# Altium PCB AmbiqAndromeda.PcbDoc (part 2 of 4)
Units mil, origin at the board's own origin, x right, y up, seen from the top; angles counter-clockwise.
Board outline 4055.04 x 2407.2 mil, 6 copper layers (Layer 1, Layer 2, Layer 3, Layer 4, Layer 5, Layer 6), stack 76.457 mil thick; 255 components, 215 nets, 1186 pads, 683 vias.
Unrouted connection lines stored in the file: 258.
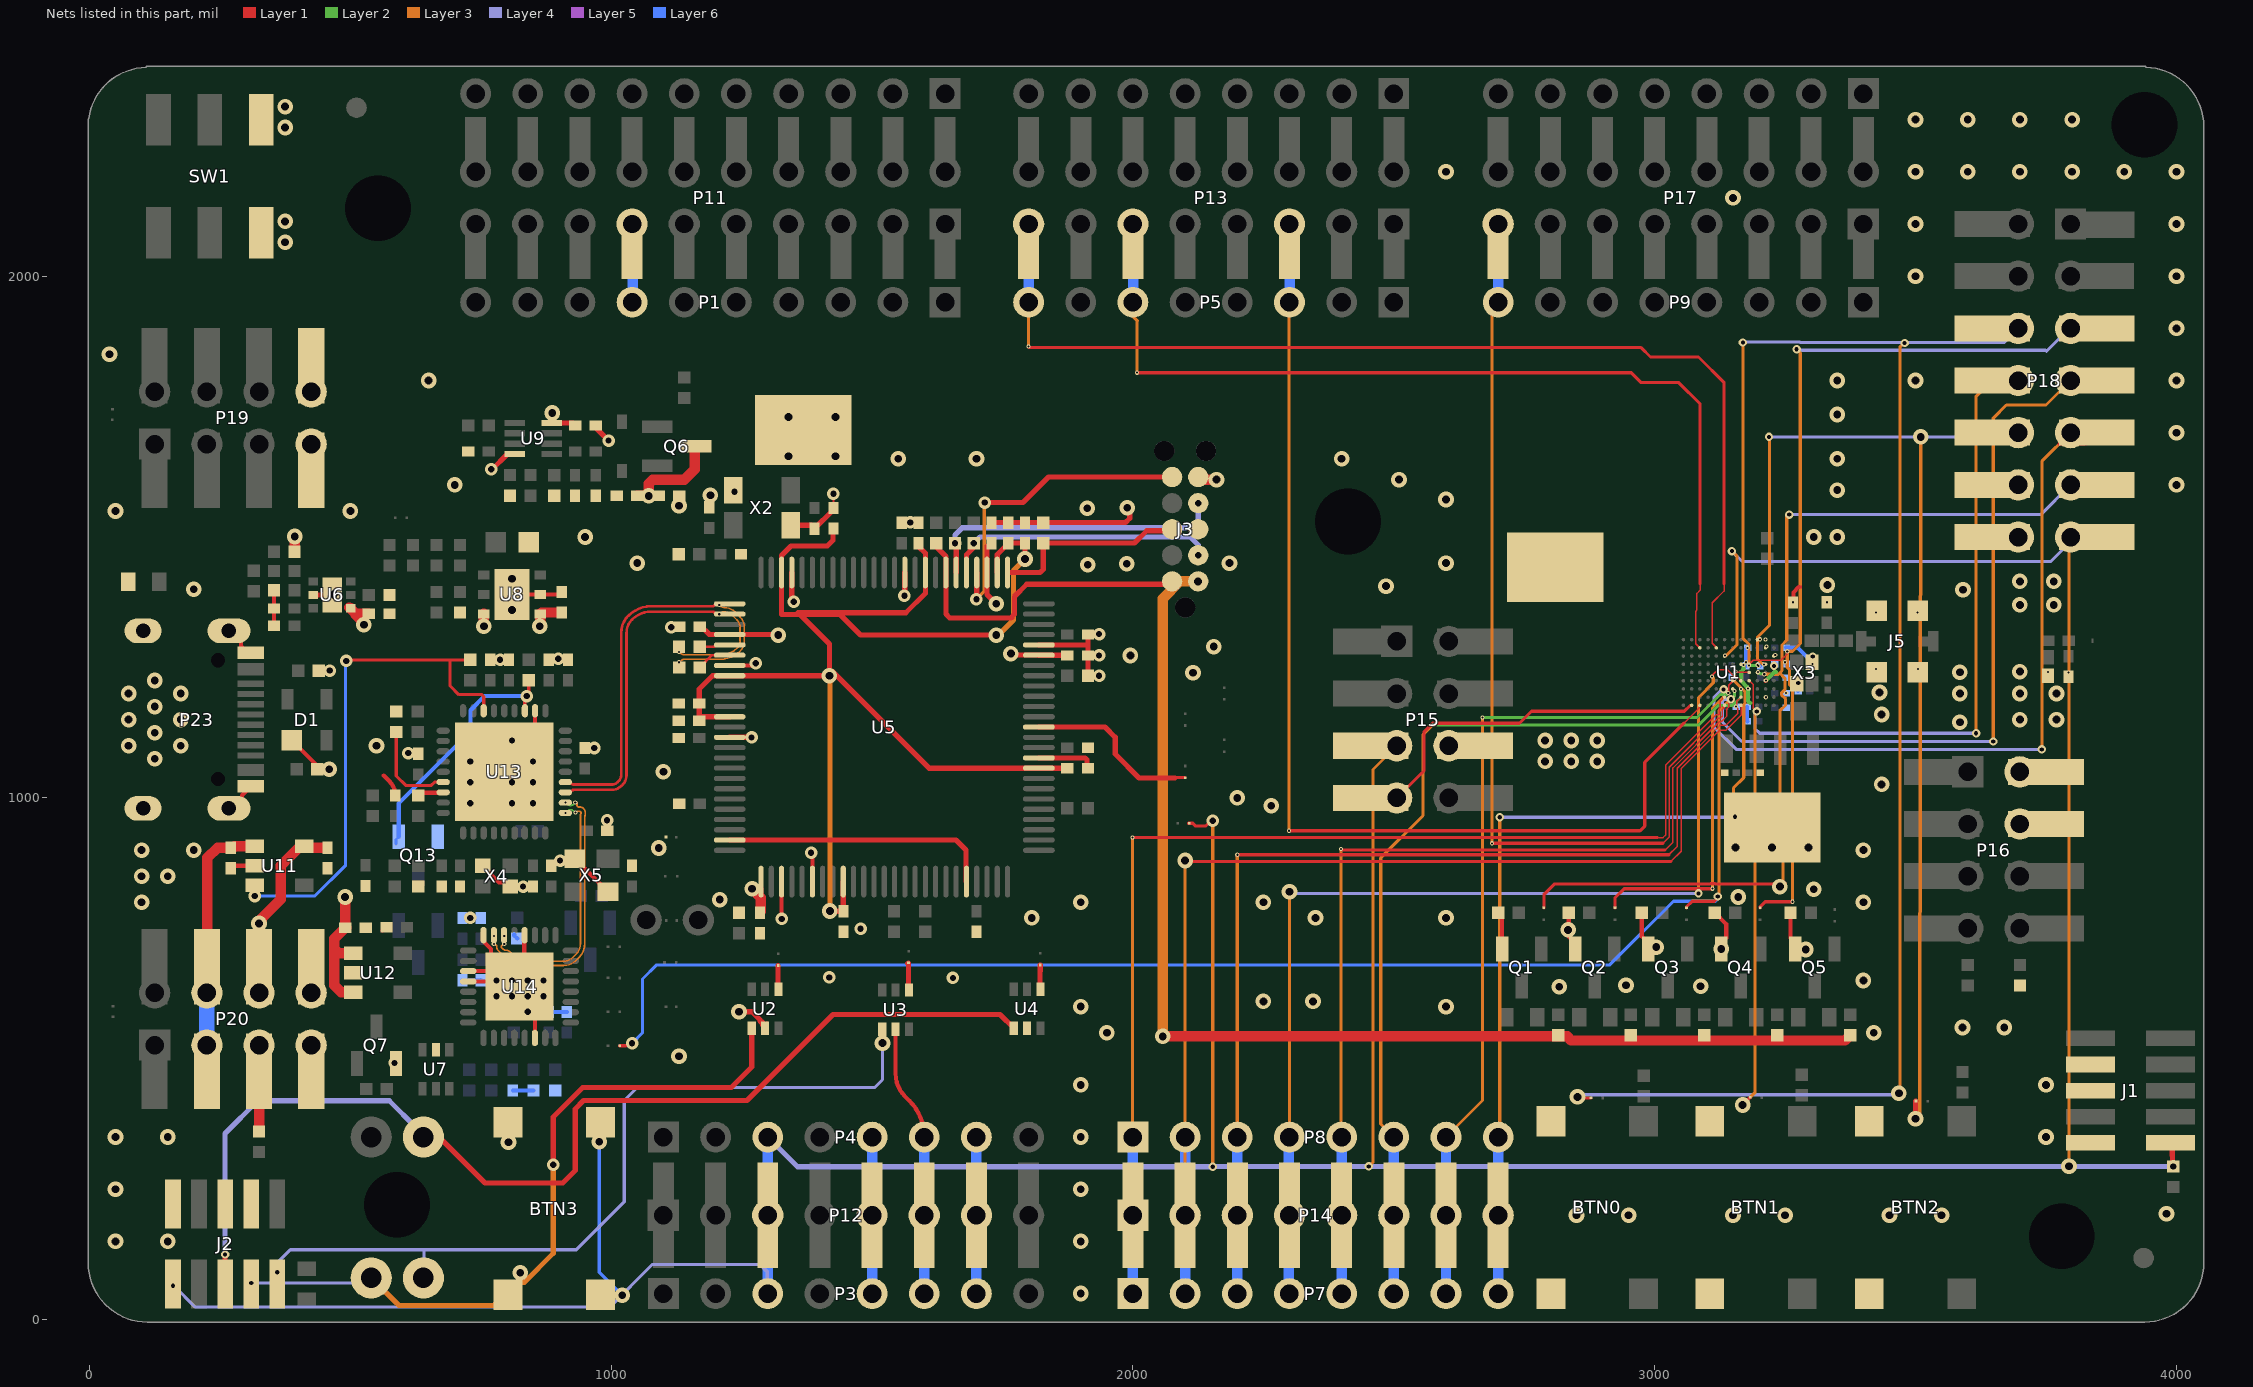
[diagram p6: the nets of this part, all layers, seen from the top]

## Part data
A1: library part ANT_PCB, "2.4G Printed Antenna"
BTN0 BTN1 BTN2 BTN3: library part TACT_4PIN, "Tactile Switch SPST-NO Top Actuated Surface Mount"
C1 C2 C3 C4 C5 C6 C7 C8 C9 C10 C11 C12 C13 C14 C15 C16 C17 C18 C19 C20 C21 C22 C23 C24 C25 C26 C27 C28 C29 C30 C31 C32 C33 C34 C35 C36 C37 C38 C39 C40 C41 C42 C43 C44 C45 C46 C47 C48 C49 C50 C51 C54 C55 C56 C57 C58 C59 C60 C61 C62 C63 C64 C65 C66 C67 C68 C69 C70 C71 C72 C73 C74 C78 C79 C80 C81 C82 C83 C84: library part CAP_CHP, "Surface Mount Unpolarized Capacitor"
D1: "Ultra low capacitance double rail-to-rail ESD protection diode"
D2 D3 D5 D6 D7 D8 D9: library part LED_SMD, "Surface Mount LED"
D70: library part SKT_SMD, "Surface Mount Diode"
FB1: library part FBD_CHP, "Surface Mount Ferrite Bead"
J1 J2: library part FTSH-105, "10 Positions Header, Unshrouded Connector 1.27mm SMD Gold"
J5: "SWD Connector Receptacle, Female Socket 50 Ohm Surface Mount Solder"
L1: library part IND_PWR, "DFE201610E-2R2M=P2"
L2: library part IND_PWR, "DFE18SAN1R0MG0L"
L3 L4 L5: library part IND_CHP, "Chip Inductor"
P1 P2: library part HDR1X10
P3 P4 P5 P6 P7 P8 P9 P10: library part HDR1X8
P11: library part SSM-110-L-DV-P-TR_2, "20 Position Receptacle, Pass Through Connector 2.54mm Gold SMD"
P12 P14: "8 Position Receptacle, Pass Through Connector 2.54mm Gold SMD"
P13 P17: library part SSM-108-L-DV-P-TR_2, "16 Position Receptacle, Pass Through Connector 2.54mm Gold SMD"
P15 P16 P19 P20: "8 Positions Header, 2 Row,Gold, Unshrouded Connector 2.54mm SMD"
P18: "14 Positions Socket Strip, Double Row Vertical 2,54mm SMD"
P21 P22: "SMT Fiducial"
P23: "USB Type-C Connector"
Q1 Q2 Q3 Q4 Q5 Q13: library part MOS_N, "N-Channel MOSFET"
Q6 Q7: library part TRAN_NPN, "Surface Mount NPN Transistor"
Q11 Q12: library part MOS_P, "P-Channel MOSFET"
R1 R2 R3 R4 R5 R6 R7 R8 R9 R10 R11 R12 R13 R14 R15 R16 R17 R18 R19 R20 R21 R22 R23 R26 R27 R28 R29 R30 R31 R32 R33 R34 R35 R36 R37 R38 R39 R40 R41 R42 R43 R44 R45 R46 R47 R48 R49 R50 R51 R52 R53 R54 R55 R56 R57 R58 R59 R60 R61 R62 R79 R80 R81 R82 R86: library part RES_CHP, "Surface Mount Resistor"
SB1 SB3 SB5 SB7 SB8 SB9 SB10 SB11 SB12 SB13 SB14 SB17 SB18 SB19 SB20 SB21 SB22 SB23 SB24 SB25 SB26 SB27 SB84: "Short-circuit soldering bridge"
SB4 SB6 SB15 SB16 SB85: "Open-circuit soldering bridge"
SW1: "Slide Switch DPDT Surface Mount 9x3.5x3.5  Pitch=2.5mm"
TP1 TP2 TP3 TP4: library part TP
TP6 TP7 TP8: library part TP, "Test Point"
U1: library part APOLLO3BP-BGA, "APOLLO3 Blue Plus", Manufacturer="Ambiq Micro"
U2 U3 U4: "2-channel analog multiplexer/demultiplexer"
U5: library part ATSAM3U2CA, "Atmel"
U6: library part NCP380, "IC CURRENT LIMIT SWITCH UDFN6"
U7: library part 74LVC2G04, "Dual Inverter"
U8: "Voltage Regulator, 1A, Low Quiescent Current  ,DFN6 Tape&Reel"
U9: library part MAX44263, "General Purpose Amplifier 2 Circuit Rail-to-Rail"
U11 U12: "Linear Voltage Regulator Positive Fixed 1 Output 3.3V 300mA SOT-23-5"
U13: library part USB2512B, "USB 2.0 High-Speed 2-Port Hub Controller"
U14: library part FT4222, "FT4222H USB2.0 TO QUADSPI/I2C BRIDGE IC"
X1: "32.768KHZ IoT OPTIMIZED SMD CRYSTA"
X2: library part XTAL_SMD_4PIN, "XTAL 12MHz ±30ppm 18pF 100 Ohm -20°C ~ 70°C SMD 3225"
X3: library part ECX-1247, "XTAL 32MHZ 8pF 20ppm  1.6mm x 1.2mm x 0.35mm SMT"
X4 X5: library part XTAL_SMD_4PIN, "Surface Mount Crystal"

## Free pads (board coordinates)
  round 60 hole 35.43: 1(1167,766) 2(1067,766)
  rect 23.62x57.09 hole 125.98 unplated: MH(553,2130) MH(589.37,220) MH(2412,1530) MH(3780,160) MH(3939,2290)

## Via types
v1: diameter 30, hole 15, Layer 1 to Layer 6, tented both sides, 227 vias
v2: diameter 8, hole 4, Layer 1 to Layer 2, tented both sides, 113 vias
v3: diameter 8, hole 4, Layer 2 to Layer 3, tented both sides, 98 vias
v4: diameter 24, hole 12, Layer 1 to Layer 6, tented both sides, 91 vias
v5: diameter 16, hole 8, Layer 3 to Layer 4, tented both sides, 71 vias
v6: diameter 8, hole 4, Layer 5 to Layer 6, tented both sides, 26 vias
v7: diameter 16, hole 8, Layer 1 to Layer 6, tented both sides, 25 vias
v8: diameter 8, hole 4, Layer 4 to Layer 5, tented both sides, 20 vias
v9: diameter 8, hole 4, Layer 1 to Layer 2, 4 vias
v10: diameter 8, hole 4, Layer 2 to Layer 3, 4 vias
v11: diameter 16/16/16/16/16/16 (per signal layer), hole 8, Layer 1 to Layer 6, tented both sides, 2 vias
v12: diameter 24/0/0/24/24/24 (per signal layer), hole 12, Layer 1 to Layer 6, tented both sides, 1 vias
v13: diameter 30/0/0/30/30/30 (per signal layer), hole 15, Layer 1 to Layer 6, tented both sides, 1 vias

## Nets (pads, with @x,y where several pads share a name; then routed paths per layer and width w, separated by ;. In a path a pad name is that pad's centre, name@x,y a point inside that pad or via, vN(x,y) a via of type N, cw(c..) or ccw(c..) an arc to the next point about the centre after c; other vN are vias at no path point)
5V_USB: C32.2 C34.2 C36.2 C50.2 C79.2 C81.2 C82.2 J3.5 P3.5 P4.5 P12.5 P20.3 P20.4 Q6.3 R19.1 U6.1 U8.1 U8.6 U9.8 U11.1 U12.1 U12.3 | length 1483.3
  Layer 1 w10: U9.8@885.93,1718.43 U9.8@886.16,1718.43 ; v1(887,1737.65) 887,1720.18 887.46,1719.73 U9.8@886.16,1718.43 ; C79.2@930.82,1713.9 926.29,1718.43 U9.8@886.16,1718.43
  Layer 1 w20: P20.4@220,720 226,726 226,885 245.69,904.69 C34.2@271,904.69 275.69,904.69 C34.2@276,905 ; P20.4@224,713 220,709 220,681.25 P20.4@225,676.25 ; C34.2@277,906 278.4,907.4 U11.1@317,907.4 ; R19.1@392.92,1471.99 R19.1@393.33,1471.99 ; R19.1@393.33,1472.01 v1(393.33,1501) ; 475.04,705 477.64,702.4 U12.1@505.76,702.4 ; v1(490,810) 490,751.16 C50.2@490.16,751 ; C50.2@492.13,750.84 491.97,751 C50.2@490.31,751 C50.2@490.16,751 ; U6.1@498,1365 U6.1@499.59,1363.41 ; U6.1@500.93,1363.41 U6.1@499.59,1363.41 ; U12.3@505.76,627.6 482.4,627.6 469,641 469,729.69 488.5,749.19 488.5,750.84 488.66,751 C50.2@490.16,751 ; v1(526,1332) 526,1334.71 510.01,1350.7 510.01,1352.99 ; C32.2@535.55,1352.99 510.01,1352.99 ; v1@755,1328 v1(755.87,1328.87) U8.6@755.87,1352.6 ; v1@864.13,1329 U8.1@864.13,1352.6 866.85,1355.31 C36.2@905,1355.31 ; C81.2@1050.19,1578.9 v1(1072,1578.9) 1072,1602 1080,1610 1140,1610 1160,1630 1160,1660 ; Q6.3@1162.91,1673.9 Q6.3@1164.8,1673.9 ; J3.5@2125,1615 2130,1620 2140,1610 v1(2160,1610) ; U6.1@499.59,1363.41 510.01,1352.99
  Layer 5 w20: v1@1072,1578 v1(1072,1578.9)
  Layer 6 w6: P20.4@225,626.25 230,621.25 230,590
  Layer 6 w20: P4.5@1495.27,354.73 P4.5@1500,350 P12.5@1500,200 P3.5@1500,50
  Layer 6 w30: P20.3@225,526.25 P20.4@225,626.25
  other v1: 863,1329
32K_NCE47_CT26_M5MOSI_RX1_GP47: P5.6 P13.11 U1.H10 | length 1877.8
  Layer 1 w3: U1.H10@3086.58,1287.7 3078.73,1295.54 3078.73,1357.73 3081,1360 3081,1392 3087,1398 3087,1410
  Layer 1 w6: v2(2008,1815) 2955,1815 2974,1796 3046,1796 3087,1755 3087,1410
  Layer 2 w6: P5.6@2000,1950 P5.6@2004.5,1945.5
  Layer 3 w6: P5.6@2004.5,1945.5 1999,1940 2002,1937 2000,1935 2001,1934 1995,1928 2008.5,1914.5 2008,1914 v2(2008,1815)
  Layer 6 w20: P5.6@2000,1950 2000.16,1950.16 P13.11@2000.16,2100
  other v3: 2008,1815
ADC0NSE9_NCE12_CT0_SCE_PDMC_CTS0_TX1_GP12: P9.8 P17.15 U1.A7 | length 1840.2
  Layer 1 w3: 3016,913 3028,925 3028,1059 3122,1153 3126.17,1153 3129.5,1156.33 3129.5,1169.31 3131.92,1171.73 3131.92,1175.56 U1.A7@3133.82,1177.46
  Layer 1 w6: v2(2688,913) 3016,913
  Layer 3 w6: v2(2688,913) 2688,1938 P9.8@2700,1950
  Layer 6 w6: P9.8@2697,1938.35 P9.8@2698,1939.35
  Layer 6 w20: P17.15@2700,2100 P9.8@2700,1950 P9.8@2702.16,1947.84
  other v3: 2688,913
ADC0PSE8_NCE13_CT2_I2SB_EXHFB_RTS0_RX1_GP13: P7.1 P8.1 P14.1 U1.B7 | length 2231.1
  Layer 1 w3: 3005,924 3016,924 3021,929 3021,1063 3117,1159 3122,1159 3123.5,1160.5 3123.5,1171.79 3125.92,1174.21 3125.92,1185.92 3133.21,1193.21 U1.B7@3133.82,1193.21
  Layer 1 w6: v2(1999,924) 3005,924
  Layer 3 w6: v2(1999,924) 1999,351 P8.1@2000,350
  Layer 6 w3: P8.1@1989,361 P8.1@2000,350
  Layer 6 w6: P8.1@1987,363 P8.1@1989,361
  Layer 6 w20: P7.1@2000,50 P14.1@2000,200 P8.1@2000,350
  other v3: 1999,924
ADC1N_NCE15_RX1_PDMD_EXXT_SWDIO_SWO_GP15: P18.7 SB3.2 SB21.1 U1.C6 | length 4239.8
  Layer 1 w3: P18.7@3776.02,1776.5 3799.52,1800 P18.7@3847.02,1800
  Layer 1 w6: SB3.2@1016.19,524.88 1027.66,524.88 ccw(c1027.66,542.31) v4(1040,530) ; SB21.1@3061,789.19 3061,791.3 3071.7,802 3114.71,802 3121,808.29 v2(3121,811)
  Layer 5 w6: P18.7@3797.02,1800 P18.7@3800.52,1796.5
  Layer 2 w6: v3(3145.97,1189.19) 3147.19,1189.19 3153,1195 v2(3153,1205)
  Layer 3 w6: v5@3123,811 3123,1166.22 v3(3145.97,1189.19) ; v5(3649,1108) 3649,1728 3674,1753 3750.02,1753 P18.7@3797.02,1800
  Layer 4 w6: v3(3145.97,1189.19) 3134.19,1189.19 3130,1185 3130,1145 3167,1108 v5(3649,1108)
  Layer 6 w6: v4(1040,530) 1060,550 1060,653 1087,680 2914,680 3036,802 3116,802 3120.62,806.62 3120.62,810.62 v2(3121,811)
  other v3: 3121,811
  other v5: 3121,811 3145.97,1189.19
  other v6: 3121,811
  other v8: 3121,811
ADC1P_NCE14_TX1_PDMC_EXHFS_SWDCK_32K_GP14: P18.9 SB20.1 U1.C7 | length 2070.7
  Layer 1 w6: SB20.1@2924,789.19 2924,808.6 2941.4,826 v2(3111,826) ; U1.C7@3132,1209.6 3132.06,1209.54 v2(3132.06,1208.1) ; P18.9@3775.02,1678 3825.02,1678 P18.9@3847.02,1700
  Layer 2 w6: v3@3131.93,1208.58 v3@3132,1208.64 ; v2(3132.06,1208.1) v3@3132.06,1208.71 ; v3@3132,1208.64 v3@3132.06,1208.71 ; v3@3132,1208.64 v3@3132,1209.57 ; v3@3132,1209.6 v3@3132.06,1209.54 ; v3@3132,1209.57 v3@3132.06,1209.51 ; v3@3132.06,1208.71 v3@3132.06,1209.51 ; v3@3132.06,1208.71 v3@3132.46,1209.11 ; v3@3132.06,1209.51 v3@3132.46,1209.11 ; v3@3132.46,1209.11 3132.99,1208.58 3133.09,1208.68 3133.32,1208.68 3134,1209.36 3133.36,1210 v3@3132.46,1209.11
  Layer 3 w6: v2(3111,826) 3111,1171.98 3132.06,1193.04 v2(3132.06,1208.1) ; P18.9@3797.02,1700 3742,1644.98 v5(3742,1093) v5@3742,1092 ; v5@3742,1092 3742,1090 3741,1091 v5@3742,1092
  Layer 4 w6: v5@3131.16,1209 v2(3132.06,1208.1) ; v5@3132,1211.84 v5@3134,1209.84 ; v5@3132.06,1208.13 3130.6,1209.6 3114,1193 3114,1135 3156,1093 v5(3742,1093) ; v5@3132.48,1208.19 3134.03,1208.19 3134.84,1209 v5@3134,1209.84 ; v2(3132.06,1208.1) 3132.16,1208 v5@3132.26,1208.1 ; v2(3132.06,1208.1) v5@3132.26,1208.1 ; v5@3132.26,1208.1 v5@3134,1209.84
  other v3: 3111,826 3132.06,1208.1
  other v5: 3132.06,1208.1
ADCSE0_NCE16_TRG0_SCCRST_CMPI0_TX0_RTS1_GP16: P18.6 SB24.1 U1.F3 | length 3275.3
  Layer 1 w6: v1@2849,424 2864,424 2865,425 SB24.1@2877.81,425
  Layer 2 w6: v3(3181,1254) 3196,1254 v2(3197,1255)
  Layer 3 w6: v5@3173,1870 3170,1873 v5(3169,1873) 3169,1306 3181,1294 v3(3181,1254) ; v1(3468,434) 3469,434 3470,435 3470,1864 3478,1872 v5(3479,1872)
  Layer 4 w6: v1(2852,427) 2856,431 v1@3467,431 ; v5(3169,1873) 3170,1874 3277.8,1874 3278.8,1873 3670.02,1873 P18.6@3697.02,1900
ADCSE1_NCE29_CT9_CTS0_CTS1_RX0_PDMD_GP29: P7.2 P8.2 P14.2 U1.A5 | length 2270.5
  Layer 1 w3: 3031,878 3051,898 3051,1056.54 3124.46,1130 3137,1130 3165.5,1158.5 3165.5,1177.28 U1.A5@3165.32,1177.46
  Layer 1 w6: v1@2106,878 3031,878
  Layer 3 w6: P14.2@2100,200 P8.2@2100,350 v1@2100,878
  Layer 6 w4: P7.2@2100,50 P7.2@2100,51
  Layer 6 w20: P7.2@2100,51 P14.2@2100,200 2100,346.5 2096.5,350 P8.2@2100,350
  other v1: 2100,880
ADCSE2_NCE11_CT31_SINT_CTS1_RX0_PDMD_GP11: P7.3 P8.3 P14.3 U1.B5 | length 2035.7
  Layer 1 w3: 3027,891 3043,907 3043,1057.03 3124.97,1139 3136.02,1139 3159.5,1162.48 3159.5,1171.52 3157.47,1173.55 3157.47,1185.36 U1.B5@3165.32,1193.21
  Layer 1 w6: v2(2200,891) 3027,891
  Layer 3 w6: P8.3@2200,350 v2(2200,891)
  Layer 6 w6: P8.3@2200,328 P8.3@2200,350
  Layer 6 w20: P7.3@2200,50 P14.3@2200,200 P8.3@2200,328
  other v3: 2200,891
ADCSE3_NCE31_CT13_RX0_SCCCLK_BLEMISO_RTS1_GP31: P7.4 P8.4 P14.4 U1.D5 | length 2060.6
  Layer 1 w3: v2(3110,1233) 3110,1234.35 3112.17,1236.53 3112.17,1236.85 3121.33,1246 3138.98,1246 3151.48,1233.5 3156.52,1233.5 U1.D5@3165.32,1224.71
  Layer 3 w6: P8.4@2300,350 v1@2300,816 ; v5(3084,817) 3084,1192.24 3112.33,1220.56 3112.33,1230.13 v3@3110,1232.46
  Layer 4 w6: v1@2300.25,817 v5(3084,817)
  Layer 6 w6: P8.4@2299,327 2300,328 P8.4@2300,350
  Layer 6 w8: P8.4@2300,350 P8.4@2308,358
  Layer 6 w20: P8.4@2299,327 2299,51 P7.4@2300,50
  other v1: 2300,820
  other v3: 3110,1233
ADCSE4_NCE32_CT15_SCCIO_EXLF_BLEMOSI_CTS1_GP32: P7.5 P8.5 P14.5 U1.B6 | length 1832.2
  Layer 1 w3: 3020,900 3035,915 3035,1057.51 3123.49,1146 3127.66,1146 3138.5,1156.84 3138.5,1171.04 3141.67,1174.21 3141.67,1183.67 3147.84,1189.84 3147.84,1190.48 3149.57,1192.21 U1.B6@3149.57,1193.21
  Layer 1 w6: v2(2399,902) 2401,900 3020,900
  Layer 3 w6: v2(2399,902) 2399,371 2409.85,360.15 2410.15,360.15 P8.5@2400,350
  Layer 6 w6: P8.5@2400,328 P8.5@2400,350
  Layer 6 w20: P7.5@2400,50 P14.5@2400,200 P8.5@2400,328
  other v3: 2399,902
ADCSE5_NCE33_32K_BLECSN_CTS0_CT23_SWO_GP33: P7.6 P8.6 P14.6 U1.C5 | length 1788.3
  Layer 2 w6: v3(2575,1140) 3085,1140 3122.27,1177.27 3149.27,1177.27 3165.32,1193.32 v2(3165.32,1208.96)
  Layer 3 w6: P8.6@2500,350 2475,375 2475,885 2556,966 2556,1121 v3(2575,1140)
  Layer 6 w10: P8.6@2494,366 2500,360 P8.6@2500,350
  Layer 6 w20: P7.6@2500,50 P14.6@2500,200 P8.6@2500,350
ADCSE6_NCE34_RTS1_CMPR2_RTS0_RX0_PDMD_GP34: P7.7 P8.7 P14.7 U1.D6 | length 1651.7
  Layer 1 w3: v2@3140.24,1201.08 3140.33,1201 v2(3141,1201) ; v2@3140.58,1201.42 3141.72,1202.56 3141.72,1215.72 3147.72,1221.72 3147.72,1221.86 3149.86,1224 3150,1224 3149.57,1224.43 U1.D6@3149.57,1224.71
  Layer 2 w6: v3(2670,1154) 3081,1154 3125.1,1198.1 3138.1,1198.1 v2(3141,1201)
  Layer 3 w6: P8.7@2600,350 2670,420 v3(2670,1154)
  Layer 6 w20: P7.7@2600,50 P14.7@2600,200 P8.7@2600,350
ADCSE7_NCE35_TX1_I2SD_CT27_RTS0_BLESTATUS_GP35: P7.8 P8.8 P14.8 U1.E4 | length 1692.2
  Layer 1 w3: v2(3155,1242) 3156,1242 3156.84,1241.16 3180.36,1241.16 U1.E4@3181.07,1240.45
  Layer 2 w6: v3(3152.91,1227.91) 3153.29,1228.29 3153.29,1239.75 3155,1241.46 v2(3155,1242)
  Layer 3 w6: P8.8@2703,358.41 v5(2703,963) ; v3(3152.91,1227.91) 3152.91,1223.6 3173,1203.51 3173,1181.56 3170.57,1179.13 3170.57,1038.85 3151,1019.27 3151,967 v5(3154,964)
  Layer 4 w6: v5(2703,963) 3153,963 v5(3154,964)
  Layer 6 w6: P8.8@2700,350 2698,352 2703.71,357.71 P8.8@2703,358.41
  Layer 6 w20: P7.8@2700,50 P14.8@2700,200 P8.8@2700,350
AT_3.3V: C20.2 C21.2 C22.2 C25.2 C35.2 J3.1 P20.5 P20.6 R27.2 R31.2 R32.2 R33.2 R34.2 R35.2 SB4.1 U5.1 U5.45 U5.53 U5.79 U11.5 | length 3106.4
  Layer 1 w10: C35.2@452.28,908.4 C35.2@456,904.69 ; C21.2@1170,1331 1188.04,1312.96 U5.79@1227.11,1312.96 1307.04,1312.96 1308,1312 v13(1320,1312) ; C22.2@1287,782.69 1287.15,782.83 U5.1@1287.15,826 ; C25.2@1729,1488.31 1727.31,1488.31 1720.22,1481.22 U5.53@1720.22,1432.05 1720.22,1389.79 v1(1738,1372.01) ; v1(1766.01,1276.63) 1763.17,1276.63 1765.8,1274 1828,1274 U5.45@1827.59,1273.59 ; U5.45@1819.63,1273.59 U5.45@1827.59,1273.59 ; C20.2@1874.31,1273 1873.73,1273.59 U5.45@1827.59,1273.59 ; J3.1@2124,1415 v1(2124.5,1415) ; J3.1@2124.5,1415.5 v1(2124.5,1415) ; J3.1@2125,1415 v1(2124.5,1415) ; R35.2@3375,545.31 R35.2@3375,546
  Layer 1 w20: R27.2@325,360.69 P20.5@325,476.25 ; v1(325,759.33) 325,762.03 330,767.03 330,769 367,806 367,870 404.4,907.4 U11.5@411.49,907.4 414.28,904.61 430.31,904.61 430.76,904.16 455,904.16 C35.2@455,904.69 ; v1(1270,826) 1287,809 C22.2@1287,782.69 ; v1(2057,543) 2832,543 2840,535 3095,535 3364.69,535 R35.2@3375,545.31
  Layer 3 w20: v1(2057,543) 2057,1382 2090,1415 v1(2124.5,1415)
  other v1: 1091,904
AT_nRST: J3.10 R12.2 U5.57 | length 629.1
  Layer 1 w10: R12.2@1623,1488.31 1623,1481 1641.48,1462.52 U5.57@1641.48,1432.05 1641.48,1352.33 1648.81,1345 1766,1345 1773,1352 1773,1386 1796.39,1409.39 2069.39,1409.39 J3.10@2075,1415
AT_PWR: R26.1 U11.3 U13.16 | length 986.4
  Layer 1 w6: v4@493.36,1266.15 494.83,1264.69 691,1264.69 ; R26.1@730,1264.69 691,1264.69 ; U13.16@755.63,1167.13 755.63,1194.49 752.12,1198 708,1198 691,1215 691,1264.69
  Layer 6 w6: v4(317,812) 432,812 491,871 491,1261.3 v4(492.18,1262.48) 493.36,1263.67 493.36,1268.64 v4@492,1270
AT_SWCLK: SB7.2 U2.4 | length 45.6
  Layer 1 w10: U2.4@1319.88,633.58 SB7.2@1319.88,678.81 ; U2.4@1320.43,633.58 U2.4@1320.66,633.81
AT_SWDIO: SB8.2 U3.4 | length 54.1
  Layer 1 w10: SB8.2@1568.48,682.41 SB8.2@1569.88,683.81 U3.4@1569.88,631.73
AT_SWO: SB10.2 U4.4 | length 46.6
  Layer 1 w10: SB10.2@1822.45,679.81 1822.45,668.91 1822.04,668.5 1822.04,634.11 U4.4@1822.57,633.58
AT_SWRST: BTN3.2 BTN3.3 J1.10 J2.10 P3.3 P4.3 P12.3 P15.5 P18.13 R3.2 SB9.2 U1.G7 | length 8478.2
  Layer 1 w6: BTN3.2@979.32,47.65 v1(1021.14,46.65) ; BTN3.3@979.32,378.35 BTN3.3@984,373.68 ; SB9.2@2106.19,951.51 2106.31,951.39 SB9.2@2108.19,951.39 2114.64,951.39 2120.03,946 2139,946 v4@2152,959 ; P15.5@2455.51,1100 2496.4,1100 P15.5@2501.01,1095.39 ; U1.G7@3133.95,1271.95 3134.64,1272.64 v3(3134.64,1273) ; P18.13@3794.16,1500 P18.13@3797.02,1500 ; P18.13@3797.02,1497.5 P18.13@3797.02,1500 ; P18.13@3847.02,1500 3825.02,1522 3797.02,1522 P18.13@3797.02,1500
  Layer 1 w10: J1.10@3988.77,339 3992.1,335.67 3992.1,314.9 3992.36,314.64 3992.36,295.32 v4(3994,293.69)
  Layer 5 w10: P18.13@3793,1490 3793,1495.98 P18.13@3797.02,1500
  Layer 3 w6: v5(2153,293) v4@2153,946 ; v5(2452,293.69) 2460,301.69 2460,1054.49 P15.5@2505.51,1100 ; v3(3134.64,1273) 3135.04,1273 3136.09,1271.95 3153,1288.86 3153,1289 3158,1294 3158,1463 v5(3148,1473) ; v1(3794,294) P18.13@3794,1485
  Layer 3 w10: P18.13@3794,1485 3797.02,1488.02 P18.13@3797.02,1500
  Layer 4 w6: v5(160,65) 162,65 203,24 997,24 1079,106 1285,106 1299,92 1299,45 1300,46 P3.3@1300,50 ; v5(3148,1473) 3168,1453 3759,1453 3797.02,1491.02 P18.13@3797.02,1500
  Layer 4 w10: P4.3@1300,350 1357,293 v5@2151,293 ; v5(2153,293) 2153.69,293.69 v5(2452,293.69) v4(3994,293.69)
  Layer 6 w6: v1(977,341) 977,90.78 v1(1021.14,46.65)
  Layer 6 w10: P4.3@1298,352 P4.3@1300,350 ; P18.13@3795,1491.96 3795,1500 P18.13@3796,1500 ; P18.13@3796,1494 3797.02,1495.02 P18.13@3797.02,1500
  Layer 6 w20: P3.3@1300,50 P12.3@1300,200 P4.3@1300,350
  other v2: 160,65 3134.64,1273
  other v3: 160,65
  other v4: 2153,956
AT_TCK: J3.4 R10.1 U5.56 | length 580.1
  Layer 1 w10: U5.56@1661.17,1432.05 R10.1@1661.17,1486.15
  Layer 4 w10: v4(1659,1488) 1659,1504 1673,1518 2110,1518 2125,1533 v4(2125,1565)
AT_TDI: J3.8 R8.1 U5.51 | length 379.2
  Layer 1 w10: U5.51@1759.59,1432.05 1822.05,1432.05 1828,1438 R8.1@1828,1488.32 2002.75,1488.32 2026.44,1512 2072,1512 J3.8@2075,1515
AT_TDO: J3.6 U5.54 | length 631.1
  Layer 1 w10: v4(1700,1381) 1700,1385.6 1700.54,1386.14 U5.54@1700.54,1432.05 ; v4(1716,1566) 1789.43,1566 1838.43,1615 J3.6@2075,1615 2075,1620.34 J3.6@2076.12,1621.46
  Layer 3 w6: v4(1700,1381) 1715,1396 v4@1715,1567
  Layer 6 w10: v4@1715,1567 v4(1716,1566)
AT_TMS: J3.2 R11.1 U5.55 | length 512.2
  Layer 1 w10: U5.55@1680.85,1432.05 1680.85,1450.85 1681,1451 1681,1466 R11.1@1693,1478
  Layer 4 w10: v4(1695,1488) 1707,1500 2110,1500 2125,1485 v4(2125,1465)
AT_USB_N: R15.2 U5.77 U13.3 | length 842.6
  Layer 1 w5.15: U13.3@912.13,1010.63 917.22,1010.63 ccw(c917.22,1018.77) 922.98,1013.01 cw(c928.73,1007.26) 928.73,1015.4 1001.07,1015.4 ccw(c1001.07,1041.19) 1019.31,1022.95 1022.21,1025.86 ccw(c1005.46,1042.61) 1029.15,1042.61 1029.15,1315.81 cw(c1066.19,1315.81) 1040,1342 cw(c1076.44,1305.56) 1076.44,1357.09 1192.79,1357.09 cw(c1192.79,1348.95) 1198.54,1354.71 ccw(c1204.29,1360.46) 1204.29,1352.33 U5.77@1227.11,1352.33
  Layer 3 w3.24: v2(1130,1280) 1130.4,1280 1132.4,1278 ccw(c1141.77,1287.37) 1141.77,1274.12 1209.9,1274.12 ccw(c1209.9,1318.1) 1241,1287 ccw(c1226.51,1301.49) 1247,1301.49 1247,1326.51 ccw(c1226.51,1326.51) 1241,1341 1231.57,1350.43 ccw(c1216,1334.87) 1216,1356.88 ccw(c1216,1346.94) 1208.98,1353.98 v3(1207,1352)
  other v2: 1207,1352
  other v3: 1130,1280
AT_USB_P: R16.2 U5.76 U13.4 | length 868.5
  Layer 1 w5.15: U13.4@912.13,1030.31 917.22,1030.31 cw(c917.22,1022.18) 922.98,1027.93 ccw(c928.73,1033.69) 928.73,1025.55 1001,1025.55 ccw(c1001,1041.35) 1012.17,1030.17 1015,1033 ccw(c1005.34,1042.66) 1019,1042.66 1019,1315.9 cw(c1065.96,1315.9) 1032.75,1349.11 1032.88,1349.23 cw(c1076.36,1305.75) 1076.36,1367.24 1192.79,1367.24 ccw(c1192.79,1375.38) 1198.54,1369.63 cw(c1204.29,1363.87) 1204.29,1372.01 U5.76@1227.11,1372.01
  Layer 3 w3.24: v2(1130,1260) 1130.4,1260 1132.4,1262 cw(c1141.77,1252.63) 1141.77,1265.88 1209.92,1265.88 ccw(c1209.92,1318.06) 1246.81,1281.16 ; v3(1207,1370) 1208.97,1368.03 ccw(c1216,1375.06) 1216,1365.12 1216.08,1365.12 cw(c1216.08,1335.05) 1237.34,1356.31 1246.86,1346.79 cw(c1226.64,1326.57) 1255.24,1326.57 1255.24,1301.49 cw(c1226.51,1301.49) 1246.82,1281.18
  other v2: 1207,1370
  other v3: 1130,1260
AT_VDDOUT: C10.2 C11.2 C12.2 C13.2 C14.2 C19.2 C23.2 C24.2 U5.9 U5.34 U5.52 U5.59 U5.73 U5.83 U5.87 | length 2936.8
  Layer 1 w10: U5.87@1227.11,1155.48 1176.16,1155.48 C13.2@1168.69,1148 C14.2@1168.69,1181 1168.69,1208.69 1194.22,1234.22 U5.83@1227.11,1234.22 v1(1418.22,1234.22) 1418.22,1294.78 1361.52,1351.48 ; v1(1419.09,783.21) 1419.62,782.69 C10.2@1444.63,782.69 ; v1@1424,1242 1608.95,1057.05 U5.34@1819.63,1057.05 1828.35,1057.05 1828.4,1057 C11.2@1874.31,1057 ; C19.2@1426,1516.31 1424.94,1515.26 1424.94,1493.77 1414.17,1483 1344.84,1483 1326.52,1464.68 U5.73@1326.52,1432.05 1326.52,1351.48 1361.52,1351.48 ; U5.9@1444.63,839.53 C10.2@1444.63,782.69 ; C10.2@1445,782.69 C10.2@1444.63,782.69 ; C12.2@1589,1488.31 1589.31,1488.31 1590,1489 1590,1481 1602.11,1468.89 U5.59@1602.11,1432.05 1602.11,1392.43 1564.47,1354.79 1358.21,1354.79 1361.52,1351.48 ; U5.52@1739.91,1432.05 1739.91,1466.25 1761,1487.35 C24.2@1761,1488.31 C23.2@1793,1488.31 v1(1793,1458) ; v1@1747.96,1312 v1(1738,1312) 1478,1312 1438.52,1351.48 1361.52,1351.48
  Layer 3 w10: v1(1419.09,783.21) v1@1419.09,1237.09 ; v1(1738,1312) 1742,1312 1771,1341 1771,1436 v1(1793,1458)
ATST1_NCE30_CT11_TX0_RTS1_BLESCK_I2SD_GP30: P18.5 SB22.1 U1.F4 | length 1880
  Layer 1 w3: U1.F4@3181.07,1256.2 3188.95,1264.08 3212.82,1264.08 3212.85,1264.05 3242.05,1264.05 3254,1276 v2(3254,1281)
  Layer 1 w4: P18.5@3798.27,1890.92 3807.34,1900 3813,1900 P18.5@3847.02,1900
  Layer 1 w6: SB22.1@3202,789.19 3202,791.3 3211.7,801 v2(3264,801) ; P18.5@3794.38,1872.81 3794.38,1881.38 3794.38,1887.03 P18.5@3798.27,1890.92
  Layer 1 w10: P18.5@3794.38,1881.38 P18.5@3813,1900
  Layer 3 w6: v2(3264,801) 3264,1211.2 3258.5,1216.7 3258.5,1245.5 3254,1250 v2(3254,1281) 3264,1281 3279,1296 3279,1853 v5(3272,1860)
  Layer 4 w6: v5(3272,1860) 3274,1858 3749.02,1858 3751.01,1856.01 3795,1900 P18.5@3797.02,1900
  other v3: 3264,801 3254,1281
CFG_SEL0: R48.2 U13.24 | length 186.3
  Layer 1 w6: R48.2@588,1128.31 R48.2@588,1126.31 588,1042 606,1024 655,1024 661.31,1030.31 U13.24@677.87,1030.31
CFG_SEL1: R47.1 U13.25 | length 50.3
  Layer 1 w8: R47.1@630,1004.69 635.31,1010 677.24,1010 U13.25@677.87,1010.63
CMPI1_NCE18_CT4_RTS0_ATST2_TX1_SCCIO_GP18: P18.8 SB25.1 U1.D4 | length 2064
  Layer 1 w3: U1.D4@3181.07,1224.71 3181.71,1224.71 3189,1217.41 3189,1212.63 ; 3188.97,1180.71 3188.97,1171.29 3192.52,1167.74 v2@3194.19,1167.74 ; 3188.97,1189.96 3188.97,1196.46 ; 3188.97,1205.4 3188.97,1212.6 ; 3189,1180.74 3189,1189.93 ; 3189,1196.49 3189,1205.37
  Layer 1 w6: v1(3168.5,411.5) 3168.5,411.69 SB25.1@3182.81,426
  Layer 3 w6: v1(3168.5,411.5) 3192,435 3192,1162.34 v2(3195.44,1165.77) ; v5(3616,1124) 3616,1770 3648,1802 3695.02,1802 P18.8@3697.02,1800 ; v2(3195.44,1165.77) 3197.66,1168 3196.06,1169.61 3194.19,1167.74 3195.44,1166.5 v2(3195.44,1165.77)
  Layer 4 w6: v2(3195.44,1165.77) 3194.96,1165.3 3195.92,1164.34 3192,1160.41 3192,1133.03 3201.03,1124 v5(3616,1124)
  other v3: 3195.44,1165.77
  other v5: 3195.44,1165.77
CMPR0_NCE19_CT6_SCCCLK_ATST1_RX1_I2SB_GP19: P18.10 SB26.1 U1.F2 | length 2302
  Layer 1 w4: v3(3209.3,1255.58) U1.F2@3212.54,1255.58 ; P18.10@3689.88,1699.13 P18.10@3690,1699
  Layer 1 w6: P18.10@3625,1702 P18.10@3627,1700
  Layer 1 w10: v1@3499.9,386.1 3499.9,419 SB26.1@3500.81,419
  Layer 2 w6: P18.10@3697.02,1700 P18.10@3697.02,1706.66
  Layer 3 w6: v5(3219,1692) 3220,1691 3220,1331 3197,1308 3197,1266 3207.42,1255.58 v3(3209.3,1255.58) v3@3210.35,1255.58 ; v1@3508,378 3508,477 ; 3508,476 v1@3509.88,1692 ; v3@3210.35,1255.58 3211.18,1255.58 3210.76,1256 v3@3210.35,1255.58
  Layer 4 w6: v5(3219,1692) v1(3510,1692) 3693.02,1692 3693.77,1691.25 3694.77,1692.25 P18.10@3697.02,1690
  Layer 6 w6: P18.10@3694.02,1703.66 3697.02,1700.66 P18.10@3697.02,1700
  other v1: 3500,385
  other v2: 3209.3,1255.58
CMPR1_NCE17_TRG1_SCCCLK_RX0_CTS1_GP17: P18.11 SB19.1 U1.E3 | length 1880.9
  Layer 1 w6: SB19.1@2787.5,789.19 2787.5,814.5 2808.25,835.25 3106.11,835.25 3106.86,836 3115.14,836 3115.89,835.25 3234.75,835.25 v1(3240,830) ; P18.11@3797.02,1600 P18.11@3847.02,1600
  Layer 2 w4: v2(3198,1241) v2@3199.08,1241 ; v3@3209.23,1237.77 v3(3210,1237)
  Layer 2 w6: v2@3199.08,1241 3202.32,1237.77 v3@3209.23,1237.77
  Layer 3 w6: v3(3210,1237) 3237,1237 3239.5,1239.5 ; v1@3251,835.25 3246,840.25 3246,913.7 3240,919.7 3240,1167.2 3251,1178.2 3251,1189.8 3242.8,1198 3242.8,1200.77 3249.5,1207.47 3249.5,1229.5 3239.5,1239.5 ; v5(3258,1543) 3253,1538 3253,1302 3244,1293 3244,1244 3239.5,1239.5
  Layer 4 w6: v5(3258,1543) 3740,1543 P18.11@3797.02,1600
CST1_NCE45_CT22_I2SD_PDMD_RX0_SWO_GP45: P5.8 P13.15 U1.H8 | length 2128.9
  Layer 1 w3: U1.H8@3118.07,1287.7 3118.07,1288.7 3110.23,1296.54 3110.23,1373.86 3133,1396.63 3133,1410
  Layer 1 w6: v2(1800,1865) 1802,1863 2974,1863 2992,1845 3084,1845 3133,1796 3133,1410
  Layer 3 w6: v2(1800,1865) P5.8@1800,1950
  Layer 6 w20: P13.15@1800,2100 P5.8@1800,1950 P5.8@1808,1958
  other v3: 1800,1865
CTS: SB14.1 U5.38 | length 339.9
  Layer 1 w6: 2080.18,1038.34 2080.65,1038.81 SB14.1@2100,1038.81
  Layer 1 w10: U5.38@1819.63,1135.79 1819.77,1135.93 1946.17,1135.93 1966,1116.11 1966,1084 2011.66,1038.34 2080.18,1038.34
CTS0_SINT_NCE4_RX1_CT17_MISP2_GP4: P15.7 U1.A11 | length 730.9
  Layer 1 w6: P15.7@2505.51,1000 2505.51,1002.5 2525.01,1022 2527.51,1022 2558,1052.49 2558,1127 2574,1143 2741,1143 2764,1166 3056.84,1166 U1.A11@3067.92,1177.08
  Layer 1 w10: P15.7@2455.51,1000 P15.7@2505.51,1000
DFSD_N: R15.1 U5.80 | length 59.1
  Layer 1 w5.15: R15.1@1169.37,1290 1196.98,1290 1199.98,1293 1214,1293 1214.27,1293.27 U5.80@1227.11,1293.27
DFSD_P: R16.1 U5.81 | length 67.2
  Layer 1 w5.15: R16.1@1169.68,1250 1193.27,1273.59 U5.81@1227.11,1273.59
DVDD: C45.2 U1.F1 | length 7.5
  Layer 1 w3: U1.F1@3228.31,1256.2 3228.48,1256.2 3229,1255.68 3228.66,1255.34 3228.62,1255.3 v2(3228.62,1253.04)
  Layer 3 w3: v5@3228.66,1252.67 v2(3228.62,1253.04) ; v5@3229,1253.34 3228.7,1253.04 v2(3228.62,1253.04) ; v5@3229.66,1253.34 3228.99,1252.67 v2(3228.62,1253.04)
  Layer 4 w3: v2(3228.62,1253.04) 3228.99,1252.67 v8@3229.66,1253.34
  other v3: 3228.62,1253.04
  other v5: 3228.62,1253.04
  other v6: 3228.62,1253.04
  other v8: 3228.62,1253.04
ENSPI: U5.21 U5.99 | length 521.9
  Layer 1 w10: U5.99@1227.11,919.25 1660.75,919.25 1680,900 1680,865.86 1680.85,865.01 1680.85,863.81 1680.54,863.49 1680.54,839.85 U5.21@1680.85,839.53
EXHF_NCE26_CT3_SCCRST_MSPI1_TX0_CTS1_GP26: P5.3 P13.5 U1.A10 | length 2138.4
  Layer 1 w3: 3055.95,1143 3085.87,1172.92 3085.87,1176.75 U1.A10@3086.58,1177.46
  Layer 1 w6: v2(2299,937) 2307,937 2972,937 2981,946 2981,1068.05 3055.95,1143
  Layer 2 w3: P5.3@2300,1935.96 P5.3@2300,1950
  Layer 3 w6: v2(2299,937) 2299,1949 P5.3@2300,1950
  Layer 6 w20: P5.3@2300,1950 2300.16,1950.16 P13.5@2300.16,2100
  other v3: 2299,937
EXT_DBG_SWCLK: J2.4 TP3.1 U2.1 | length 1406.4
  Layer 1 w10: v4(889,297) 889,388.48 945.52,445 1230,445 1269.25,484.25 U2.1@1269.25,558.78
  Layer 5 w10: TP3.1@510,78.65 TP3.1@510,80
  Layer 3 w10: TP3.1@540,80 593,27 775.03,27 819.53,71.5 833.15,71.5 889,127.35 v4(889,297)
  Layer 4 w6: v7(310,70) TP3.1@542,70
  Layer 6 w10: TP3.1@510,75 TP3.1@510,80
EXT_DBG_SWDIO: J2.2 TP2.1 U3.1 | length 1590.6
  Layer 1 w10: U3.1@1519.41,556.93 1520,556.34 v1(1520,530)
  Layer 4 w6: v7(360,91) 360,109 385,134 641,134 ; TP2.1@640,80 641,81 641,134 ; v1(1520,530) 1520,460 1505,445 1050,445 1025,420 1025,226 933,134 641,134
  Layer 6 w10: v7(360,91) v7@362,91
EXT_DBG_SWO: J2.6 TP4.1 U4.1 | length 2060.5
  Layer 1 w10: J2.6@260,68.23 v7(260,125) ; TP4.1@665,355 758,262 907,262 931,286 931,404 947,420 1260,420 1425,585 1745.17,585 U4.1@1771.39,558.78
  Layer 4 w10: v7(260,125) 260,357 322.5,419.5 574.5,419.5 TP4.1@625.85,368.15
FTDI_PWR: Q13.1 R45.1 U13.12 | length 496.4
  Layer 1 w6: U13.12@834.37,1167.13 834.37,1191.5 v4(838.19,1195.31) 842,1199.13 R45.1@842,1225.32
  Layer 6 w6: Q13.1@587.47,911.47 587.47,920.3 Q13.1@592.6,925.43
  Layer 6 w8: Q13.1@592.6,925.43 592.6,989.6 730,1127 730,1168 757.31,1195.31 v4(838.19,1195.31)
FTDI_USB_N: U13.1 U14.22 | length 490.5
  Layer 2 w3.24: v10(795,720) v9(795,735) ; v9(912,971) v9@913.53,972.53 ; v9(912,971) 915.64,974.61 cw(c922,968.26) 922,977.25 cw(c922,968.35) 928.29,974.64 931.2,971.73 v10(931.4,971.73)
  Layer 3 w3.24: v10(795,720) ccw(c795,716.89) 792.8,719.09 792.09,718.38 cw(c791.01,719.46) 791.01,717.94 790.07,716.99 ccw(c792.36,714.7) 789.12,714.7 ccw(c792.36,714.7) 790.06,712.41 791.84,710.63 ccw(c798.42,717.21) 798.42,707.91 798.74,707.91 cw(c798.74,697.83) 805.86,704.96 813.37,697.45 ccw(c838.61,722.69) 838.61,687 909.1,687 ccw(c909.1,710.9) 926,694 932.51,700.51 ccw(c912.03,721) 941,721 941,967.84 cw(c942.97,967.84) 941.58,969.23 ccw(c940.18,970.63) 942.15,970.63 942.15,971.15 ccw(c938.92,971.15) 941.21,973.44 ccw(c938.92,971.15) 938.92,974.39 937.23,974.39 ccw(c937.23,969.85) v10@934.02,973.06
FTDI_USB_P: U13.2 U14.23 | length 533.5
  Layer 1 w3.24: v9(912,991) U13.2@912.13,990.94 U13.2@912.13,990.94
  Layer 2 w3.24: v10(775,720) v9(775,735) ; v9(912,991) cw(c912,987.89) 914.2,990.09 916.55,987.74 ccw(c922,993.2) 922,985.48 ccw(c922,994.38) 928.29,988.09 931,990.8 v10(931,991)
  Layer 3 w3.24: v10(775,720) cw(c775,716.89) 777.2,719.09 777.91,718.38 ccw(c778.99,719.46) 778.99,717.94 779.93,716.99 cw(c777.64,714.7) 780.88,714.7 780.88,712.99 ccw(c788.24,712.99) 783.03,707.8 788.21,702.62 ccw(c795.33,709.75) 795.33,699.67 cw(c795.33,689.59) 802.45,696.73 809.96,689.22 ccw(c835.2,714.45) 835.2,678.76 909.14,678.76 ccw(c909.14,710.81) 931.8,688.15 938.4,694.75 ccw(c912.24,720.91) 949.24,720.91 949.24,964.43 cw(c951.21,964.43) 949.81,965.82 ccw(c948.42,967.21) 950.39,967.21 950.39,971.2 ccw(c939.04,971.2) 947.07,979.23 946.27,980.02 ccw(c939.99,973.74) 939.99,982.62 937.65,982.62 cw(c937.65,985.86) 935.36,983.57 cw(c937.65,985.86) 934.41,985.86 v10@934.41,991
GND: BTN0.1 BTN0.4 BTN1.1 BTN1.4 BTN2.1 BTN2.4 BTN3.1 BTN3.4 C1.1 C2.1 C3.1 C4.1 C5.1 C6.1 C7.1 C8.1 C9.1 C10.1 C11.1 C12.1 C13.1 C14.1 C15.1 C16.1 C17.1 C18.1 C19.1 C20.1 C21.1 C22.1 C23.1 C24.1 C25.1 C26.1 C27.2 C28.2 C29.1 C30.1 C31.1 C32.1 C33.1 C34.1 C35.1 C36.1 C37.1 C38.1 C39.2 C40.2 C42.2 C43.2 C44.2 C45.1 C46.2 C47.2 C48.1 C49.1 C50.1 C51.1 C54.1 C55.2 C56.2 C57.1 C58.1 C59.1 C60.1 C61.1 C62.1 C63.1 C64.1 C65.1 C66.1 C67.2 C68.2 C69.1 C70.1 C71.1 C72.1 C73.1 C74.1 C78.1 C79.1 C81.1 C82.1 C83.1 C84.1 D1.1 D2.1 J1.3 J1.5 J1.9 J2.3 J2.5 J2.9 J3.3 J5.3 L5.1 P1.7 P3.6 P3.7 P4.6 P4.7 P11.13 P12.6 P12.7 P15.6 P16.2 P16.4 P18.12 P18.14 P19.7 P19.8 P20.7 P20.8 P23.A1 P23.A12 P23.B1 P23.B12 P23.MH@102.68,979.92 P23.MH@102.68,1320.08 P23.MH@267.25,979.92 P23.MH@267.25,1320.08 Q1.2 Q2.2 Q3.2 Q4.2 Q5.2 Q7.2 Q13.2 R2.1 R8.2 R13.1 R14.2 R17.1 R20.2 R28.1 R30.1 R39.1 R40.1 R41.1 R43.1 R44.1 R48.1 R49.1 R51.1 R52.1 R55.1 R56.1 R62.1 R81.1 R82.1 R86.1 SW1.1 SW1.4 TP6.1 TP7.1 TP8.1 U1.B2 U1.C4 U1.D2 U1.F5 U1.G1 U1.H2 U1.J2 U1.J3 U2.2 U3.2 U4.2 U5.3 U5.6 U5.35 U5.46 U5.61 U5.72 U5.82 U5.89 U6.5 U6.7 U7.2 U8.2 U8.7 U9.4 U11.2 U12.2 U13.11 U13.37 U14.6 U14.20 U14.24 U14.27 U14.28 U14.33 X2.2 X2.4 X3.2 X3.4 X4.2 X4.4 X5.2 X5.4 | length 4440
  Layer 1 w3: U6.7@456,1389 456.75,1389.75 v1(467.75,1389.75) U6.7@464,1386 ; v4(584.66,492) 586.22,492 Q7.2@587.4,490.82 ; C79.1@970,1710 970.19,1710.19 C79.1@970.19,1713.9 ; X2.4@1233.61,1589.64 v4(1236.25,1587) ; C19.1@1426,1555.69 v4(1426,1583)
  Layer 1 w8: P23.MH@267.25,979.92 274.35,979.92 292.48,998.05 292.48,1005.15 302.07,1014.73 302.07,1026.05 303.97,1027.95 P23.B1@309.27,1027.95 ; P23.MH@267.25,1320.08 272.17,1320.08 290.3,1301.95 290.3,1291.03 296.06,1285.27 296.06,1273.95 297.96,1272.05 P23.B12@309.27,1272.05 ; C34.1@271,865.32 275.68,870 U11.2@317,870 ; C30.1@353.55,1329.99 C31.1@353.55,1362.99 R17.1@353.55,1397.99 ; D1.1@387.47,1110.63 436.68,1061.42 R43.1@436.68,1055 ; R44.1@439.68,1244 R44.1@445,1249.32 ; U12.2@504.07,663.32 U12.2@505.76,665 ; C51.1@561.5,746.16 567.35,752 C51.1@569.31,752 571.28,752 577.13,757.84 C51.1@577.13,758.13 ; 564,1043 574.52,1032.48 cw(c546.72,1004.69) C54.1@586.03,1004.69 ; C56.2@710,830.31 C56.2@710,832.28 ; U14.28@725.79,648.27 725.29,648.27 725.21,648.35 U14.33@814.29,648.35 ; U14.27@725.79,667.95 U14.33@794.68,667.95 ; X4.4@753.43,869.69 754.41,869.69 764.19,859.91 764.19,858.92 784.93,838.18 798.71,838.18 X4.2@806.57,830.32 ; U14.24@757.22,722.78 769.3,710.7 769.3,693.34 U14.33@794.68,667.95 ; C62.1@767,1265.69 C62.1@768,1264.69 ; U13.37@795,1050 795,1055 U13.37@854.06,1114.06 ; U8.7@810,1390 U8.2@864.13,1390 900.32,1390 C36.1@905,1394.69 ; U14.20@833.48,737.43 U14.20@834.06,736.85 833.33,736.12 833.33,647.54 U14.33@824.21,638.43 U14.33@814.29,648.35 ; U14.6@853.74,540 U14.33@853.74,600 ; U13.11@854.06,1167.13 U13.37@854.06,1114.06 ; U13.37@870,1130 U13.37@854.06,1114.06 ; C65.1@885,1266.69 C63.1@920,1266.69 ; X5.4@930,882.99 931.97,882.99 945.69,869.28 945.69,868.09 978.09,835.69 978.09,833.72 991.81,820 X5.2@993.78,820 X5.2@994,820 ; U5.82@1227.11,1253.9 1268.57,1253.9 1272.67,1258 v4(1277,1258) ; C22.1@1282,743 1282.31,743 cw(c1282.31,740.32) C22.1@1285,740.32 ; U2.2@1294.84,558.78 1298.72,562.65 U2.2@1298.72,567.63 ; U5.3@1326.52,839.53 1326.52,768 v4(1327,768) ; v4(1383,895) 1385.57,892.43 U5.6@1385.57,839.53 ; U3.2@1545,556.93 1545,471.46 ccw(c1606.46,471.46) 1563,428 1571.01,419.99 cw(c1501.02,350) P4.6@1600,350 ; R28.1@2700.31,780 2707.6,772.72 Q1.2@2707.6,710.43 ; R30.1@2837,781.69 R30.1@2835.31,780 2835.31,734.53 2847.6,722.24 Q2.2@2847.6,710.43 ; R39.1@2975.31,780 2975.31,734.53 2987.6,722.24 Q3.2@2987.6,710.43 ; R40.1@3115.31,780 3137,758.32 3137,731.65 3127.6,722.24 v1(3127.6,710.43) 3129.57,710.43 Q4.2@3130,710 ; U1.D2@3212.56,1224.71 3212.71,1224.71 v2(3213,1225) ; R41.1@3260.31,780 3260.31,731.6 3269.67,722.24 Q5.2@3269.67,710.43 ; C39.2@3265,1374.69 3265.81,1375.5 3265.81,1393.81 3276,1404 3278,1404 ; v1(3289.6,709.43) 3291.57,709.43 v1@3292,709 ; X3.2@3301.58,1260.37 3301.58,1257.96 v2(3302.84,1256.7) ; v7(3303,1271) 3306,1271 X3.2@3308,1269 ; J5.3@3425.63,1240.94 J5.3@3434.68,1250 ; U14.33@794.68,667.95 U14.33@814.29,648.35
  Layer 1 w10: U6.5@428.89,1389 455,1389 U6.7@456,1390 ; v4@771,1629 801.37,1659.37 U9.4@815.07,1659.37 ; C79.1@970,1710 v4(995,1685) ; R14.2@1129,1467.31 R14.2@1129.31,1467 ; U5.89@1227.11,1116.11 1268.89,1116.11 v4(1269,1116) ; v1(1245,590) 1270.01,590 1285.13,574.89 1285.13,572.35 1287.47,570 1290,570 1290,564.68 1294.84,559.84 U2.2@1294.84,558.78 ; X2.2@1343.84,1522.71 1383.29,1522.71 C27.2@1389.77,1516.23 ; U5.72@1346.2,1432.05 1346.2,1379.8 v4(1350,1376) ; C27.2@1389.72,1516.18 C27.2@1389.77,1516.23 ; C19.1@1424,1553 1424,1550.45 C27.2@1389.77,1516.23 ; C16.1@1557,1527 1557.68,1527.69 C12.1@1589,1527.69 ; v4(1562,1387.48) 1562.74,1386.74 U5.61@1562.74,1432.05 ; C25.1@1729,1527.69 C24.1@1761,1527.69 C23.1@1793,1527.69 1985.68,1527.69 1994,1536 1994,1551.28 v1(1989.17,1556.1) ; U5.35@1819.63,1076.73 1908.27,1076.73 1912,1073 C11.1@1912,1057 ; U5.46@1819.63,1293.27 1913.68,1293.27 ; C26.1@1913.68,1313 1913.68,1293.27 ; 1913.73,1293.27 1914,1293 ; R13.1@1916,1232 1913.68,1234.32 C20.1@1913.68,1273 1913.68,1293.27 ; C42.2@3795.22,1238.25 C42.2@3795.28,1238.19
  Layer 2 w8: v2(3170,1255) 3170,1246.56 3166,1242.56 3166,1223.83 3176.32,1213.51 3176.32,1212.68 v2(3179,1210) 3179,1186 3183,1182 ; v2(3213,1225) 3214,1226 3214.56,1226 3221,1232.44 3221,1233 3229.49,1241.49 3232.63,1241.49
  Layer 6 w8: 725.79,650 749.37,650 C73.1@750,650.63 ; C66.1@812,439.32 R56.1@851,439.32 ; R52.1@814,738 814,736.63 R52.1@820,730.63 ; v4(840,590) 876.31,590 878.31,588 C70.1@880,589.69 897.68,589.69 897.84,589.84 914.84,589.84 C69.1@915,589.69 ; v6(3148,1230.98) C2.1@3149.02,1230.98 ; v6(3175,1260) 3175,1253.25 3175.23,1253.02 C3.1@3175,1253.02 3175,1285.4 3177.3,1287.7 v6(3178.04,1287.7) ; C8.1@3177.04,1174.46 3177.04,1147.28 C7.1@3177.28,1147.04 ; v6(3199,1253) C9.1@3202,1253.02 ; v6(3250,1260) 3251.81,1258.19 C45.1@3251.81,1256.7 ; C38.1@3251.84,1287.7 3274.3,1287.7 3294.75,1267.25 3294.75,1259 3297.05,1256.7 C43.2@3297.84,1256.7 ; C44.2@3274.79,1204.7 3274.9,1204.8 3274.9,1219.9 v6(3275,1220)
  Layer 6 w20: P1.7@1040,1950 1040,1957 1041,1958 1041,2099 P11.13@1040,2100 ; P3.6@1600,50 P12.6@1600,200 P4.6@1600,350 ; P3.7@1700,50 P12.7@1700,200 P4.7@1700,350
  other v1: 1900,50 825.49,90 50,150 150,150 1900,150 2850,200 2950,200 3150,200 3250,200 3450,200 3550,200 3981,203 50,250 1900,250 803,340 50,350 150,350 1900,350 3750,350 1900,450 3750,450 1130,505 1950,550 3420,550 3590,560 3670,560 1900,600 2600,600 2250,610 2345,610 2817,638 3088,639 2945,641 3400,650 3003,714 2834,747 1806,770 2350,770 2600,770 100,800 1900,800 2250,800 3400,800 1208,805 3160,810 3305,825 100,850 150,850 100,900 200,900 3400,900 3155,905 3225,905 3295,905 2265,985 2200,1000 3435,1026 1100,1050 459.43,1055 2790,1070 2840,1070 2890,1070 125,1075 75,1100 175,1100 550,1100 2790,1110 2840,1110 2890,1110 125,1125 3585,1145 75,1150 175,1150 3700,1150 3770,1150 3435,1160 125,1175 75,1200 175,1200 3585,1200 3700,1200 3770,1200 3431,1202 125,1225 2115,1240 3585,1241 3700,1242 1995,1273 2155,1290 810,1360 3700,1370 3765,1370 3591,1399 200,1400 2485,1406 3331,1408 3700,1415 3765,1415 810,1420 1913.39,1446.85 1988.19,1448.82 1050,1450 2185,1450 2600,1450 950,1500 3305,1500 3350,1500 50,1550 500,1550 1912.4,1555.12 1130,1560 2600,1572 1190,1580 3350,1590 700,1600 4000,1600 2510,1610 1550,1650 1700,1650 2400,1650 3350,1650 1340,1655 1430,1655 4000,1700 1340,1730 1430,1730 3350,1735 650,1800 3350,1800 3500,1800 4000,1800 38.39,1850.39 4000,1900 3500,2000 4000,2000 375,2065 3500,2100 4000,2100 375,2105 3150,2150 2600,2200 3500,2200 3600,2200 3700,2200 3800,2200 3900,2200 4000,2200 375,2285 3500,2300 3600,2300 3700,2300 3800,2300 375,2325
  other v2: 3213,1193 3275,1220 3793,1240 3754,1241 3424,1247 3505,1247 3231,1274 3214,1290 3202,1304 3212.56,1303.45 3424,1355 3504,1355 3265.4,1375.09 3330,1375
  other v3: 3275,1220
  other v4: 780,620 810,620 840,620 870,620 780,650 810,650 840,650 870,650 1655,655 1418,656 1478,749 730,770 831,830 902,880 992,957 730,990 810,990 850,990 730,1030 810,1030 850,1030 730,1070 850,1070 611,1086 967.22,1095.69 810,1110 1935,1234 460.43,1244 787,1265 898.22,1266.69 1935,1273 1935,1314 1115,1327 1573,1528 770,1630
  other v5: 3275,1220
  other v6: 3156.02,1175 3252.02,1201
  other v8: 3275,1220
